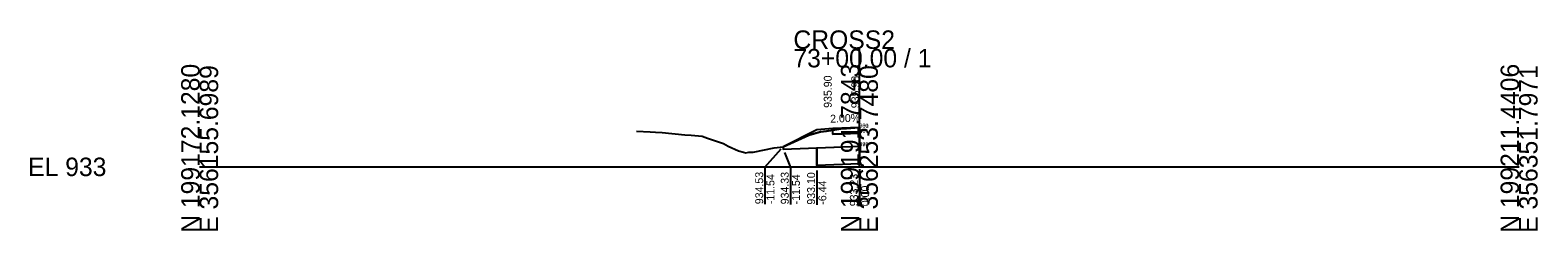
# Model space of a CAD drawing. Extents: x -26 to 203, y -10 to 14021.
# Drawn here: x -25.7 to 202.8, y 13990.3 to 14020.7 of the extents above; entities that cross this region are included whole.
import ezdxf

# ---------------------------------------------------------------- set-up
doc = ezdxf.new("R2010")
doc.units = 0
for name, color, linetype in [('Default', 7, 'Continuous'), ('P_E_XS_Ground', 7, 'Continuous'), ('P_XS', 7, 'Continuous'), ('P_XS_Bold', 7, 'Continuous'), ('P_XS_EAR_CommonGrnd', 7, 'Continuous'), ('P_XS_Lane', 7, 'Continuous'), ('P_XS_Rock', 7, 'Continuous')]:
    doc.layers.add(name, color=color, linetype=linetype)

msp = doc.modelspace()

# ---------------------------------------------------------------- linework, layer by layer
at = {"layer": 'Default'}
for p, q in [((100, 14000), (100, 14017.87)), ((0, 14000), (100, 14000)), ((100, 14000), (200, 14000))]:
    msp.add_line(p, q, dxfattribs=at)
at = {"layer": 'P_E_XS_Ground'}
for p, q in [((66.22, 14005.43), (68.31, 14005.3)), ((68.31, 14005.3), (69.09, 14005.24)), ((69.09, 14005.24), (70.11, 14005.19)), ((70.11, 14005.19), (73.53, 14004.87)), ((73.53, 14004.87), (74.48, 14004.78)), ((74.48, 14004.78), (76.15, 14004.67)), ((76.15, 14004.67), (76.99, 14004.36)), ((91.22, 14004.27), (92.34, 14004.82)), ((92.34, 14004.82), (94.11, 14005.3)), ((94.11, 14005.3), (95.04, 14005.43)), ((95.04, 14005.43), (97.49, 14005.82)), ((97.49, 14005.82), (98.06, 14005.83)), ((98.06, 14005.83), (99.97, 14005.96)), ((99.97, 14005.96), (100.02, 14005.96)), ((76.99, 14004.36), (79.39, 14003.53)), ((79.39, 14003.53), (80.1, 14003.15)), ((80.1, 14003.15), (81.66, 14002.45)), ((81.66, 14002.45), (82.45, 14002.21)), ((82.45, 14002.21), (82.8, 14002.13)), ((82.8, 14002.13), (83.22, 14002.24)), ((83.22, 14002.24), (83.92, 14002.23)), ((83.92, 14002.23), (87.1, 14002.87)), ((87.1, 14002.87), (88.46, 14003.05)), ((88.46, 14003.05), (91.22, 14004.27))]:
    msp.add_line(p, q, dxfattribs=at)
at = {"layer": 'P_XS'}
for p, q in [((96, 14004.96), (96, 14005.8)), ((96, 14004.96), (100, 14005.12)), ((100, 14005.12), (100, 14005.96)), ((100, 14005.12), (100, 14003.12)), ((88.46, 14002.66), (100, 14003.12)), ((88.46, 14003.05), (88.46, 14002.66)), ((93.56, 14002.87), (93.56, 14000.2)), ((100, 14003.12), (100, 14000.45)), ((100, 14000.45), (93.56, 14000.2))]:
    msp.add_line(p, q, dxfattribs=at)
at = {"layer": 'P_XS_EAR_CommonGrnd'}
for points in [[(92.34, 14004.82), (94.11, 14005.3), (95.04, 14005.43), (96, 14005.58), (96, 14005.8), (93.56, 14005.6), (88.46, 14003.05), (91.22, 14004.27)], [(88.46, 14003.05), (88.46, 14002.66), (93.56, 14002.87), (100, 14003.12), (100, 14005.12), (96, 14004.96), (96, 14005.58), (95.04, 14005.43), (94.11, 14005.3), (92.34, 14004.82), (91.22, 14004.27)], [(99.97, 14005.96), (100, 14005.96), (96, 14005.8), (96, 14005.58), (97.49, 14005.82), (98.06, 14005.83)], [(99.97, 14005.96), (100, 14005.96), (100, 14005.12), (96, 14004.96), (96, 14005.58), (97.49, 14005.82), (98.06, 14005.83)], [(100, 14000.45), (93.56, 14000.2), (93.56, 14002.87), (100, 14003.12)]]:
    msp.add_lwpolyline(points, close=True, dxfattribs=at)
at = {"layer": 'P_XS_Lane'}
for p, q in [((93.56, 14005.6), (88.46, 14003.05)), ((96, 14005.8), (93.56, 14005.6)), ((96, 14005.8), (100, 14005.96))]:
    msp.add_line(p, q, dxfattribs=at)
at = {"layer": 'P_XS_Rock'}
for p, q in [((85.67, 13999.94), (88.16, 14002.71)), ((85.67, 13999.94), (85.67, 13994.34)), ((88.66, 14002.15), (89.54, 13999.92)), ((89.54, 13999.92), (89.54, 13994.32)), ((93.53, 13999.47), (93.53, 13994.27)), ((100.01, 13999.63), (100.01, 13994.03))]:
    msp.add_line(p, q, dxfattribs=at)

# ---------------------------------------------------------------- texts
at = {"layer": 'Default'}
for s, p in [('CROSS2', (90, 14017.87)), ('73+00.00 / 1', (90, 14015.07)), ('EL 933', (-26, 13998.6))]:
    msp.add_text(s, height=2.8, dxfattribs=at).set_placement(p)
for s, p in [('N 199172.1280', (0, 13990)), ('E 356155.6989', (2.8, 13990)), ('N 199191.7843', (100, 13990)), ('E 356253.7480', (102.8, 13990)), ('N 199211.4406', (200, 13990)), ('E 356351.7971', (202.8, 13990))]:
    msp.add_text(s, height=2.8, rotation=90, dxfattribs=at).set_placement(p)
at = {"layer": 'P_XS_Bold'}
for s, p in [('951', (100, 14005.95)), ('9', (100, 14005.95)), ('900', (100, 14005.95)), ('951', (100, 14005.95)), ('9', (100, 14005.95)), ('900', (100, 14005.95)), ('961', (100, 14005.12)), ('961', (100, 14005.12)), ('971', (100, 14003.12)), ('998', (100, 14003.12)), ('971', (100, 14003.12)), ('998', (100, 14003.12))]:
    msp.add_text(s, height=0.6, dxfattribs=at).set_placement(p)
at = {"layer": 'P_XS_Rock'}
for s, rotation, p in [('935.90', 90, (95.81, 14008.94)), ('935.98', 90, (99.98, 14008.88)), ('2.00%', 2.2906, (95.59, 14006.68)), ('934.53', 90, (85.42, 13994.34)), ('-11.54', 90, (87.12, 13994.34)), ('934.33', 90, (89.29, 13994.32)), ('-11.54', 90, (90.99, 13994.32)), ('933.10', 90, (93.28, 13994.27)), ('-6.44', 90, (94.98, 13994.27)), ('933.23', 90, (99.76, 13994.03)), ('0.00', 90, (101.46, 13994.03))]:
    msp.add_text(s, height=1.2, rotation=rotation, dxfattribs=at).set_placement(p)

doc.saveas('drawing.dxf')
